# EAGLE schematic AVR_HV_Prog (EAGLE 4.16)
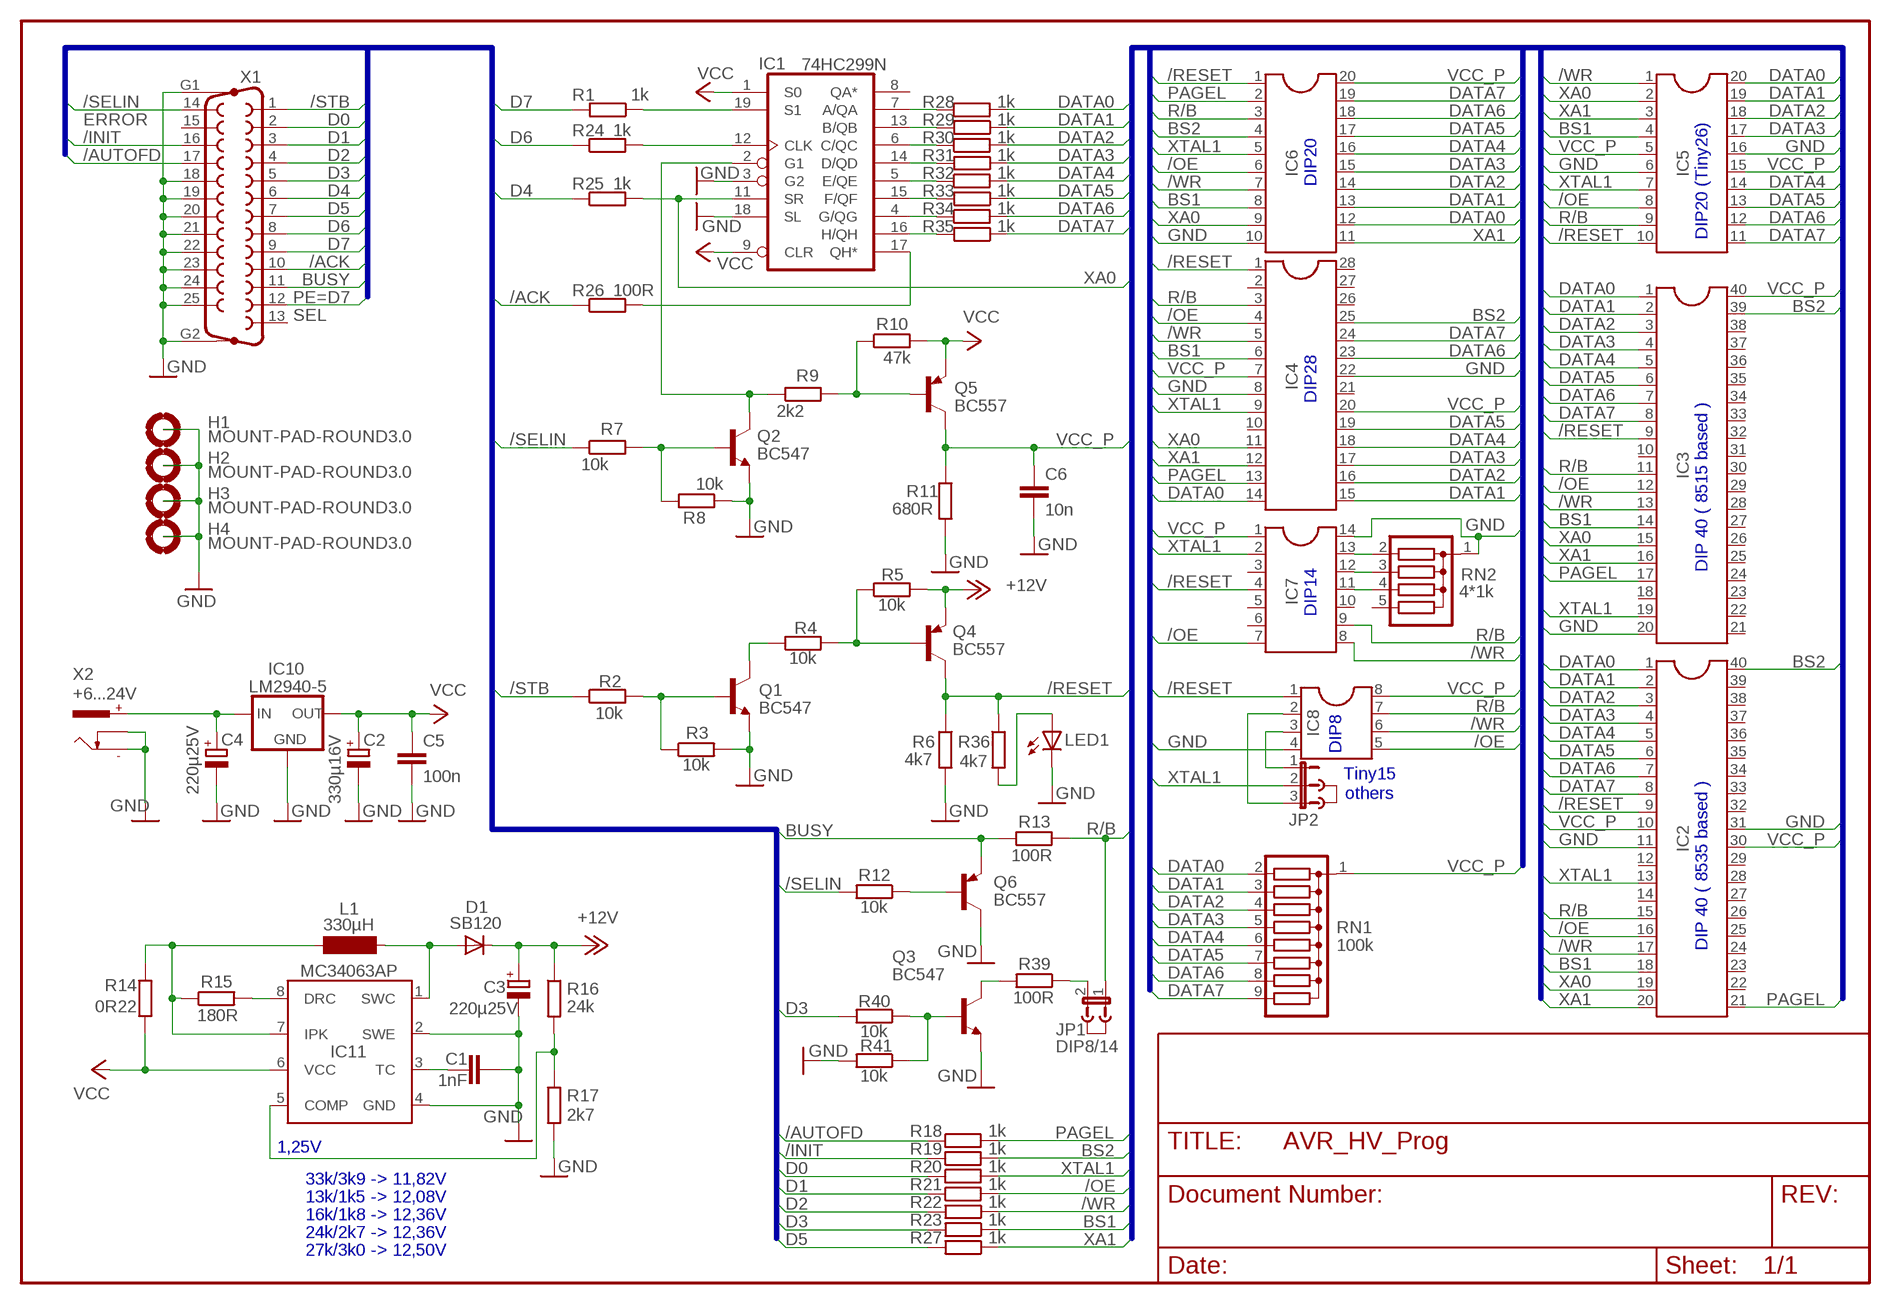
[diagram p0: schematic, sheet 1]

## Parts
C1  1nF  C-EU025-025X050  [C025-025X050]
C2  330µ16V  CPOL-EUE3.5-8  [E3,5-8]
C3  220µ25V  CPOL-EUE3.5-8  [E3,5-8]
C4  220µ25V  CPOL-EUE3.5-8  [E3,5-8]
C5  100n  C-EU050-024X044  [C050-024X044]
C6  10n  C-EU050-024X044  [C050-024X044]
D1  SB120  DIODE-D-2.5  [D-2.5]
H1  MOUNT-PAD-ROUND3.0  [3,0-PAD]
H2  MOUNT-PAD-ROUND3.0  [3,0-PAD]
H3  MOUNT-PAD-ROUND3.0  [3,0-PAD]
H4  MOUNT-PAD-ROUND3.0  [3,0-PAD]
IC1  74HC299N  [DIL20]
IC2  DIL40  [DIL40]
IC3  DIL40  [DIL40]
IC4  DIL28-3  [DIL28-3]
IC5  DIL20  [DIL20]
IC6  DIL20  [DIL20]
IC7  DIL14  [DIL14]
IC8  DIL8  [DIL08]
IC10  LM2940-5  78XXS  [78XXS]
IC11  MC34063AP  [DIL-08]
J1  JUMPER  [JUMP]
J2  JUMPER  [JUMP]
JP1  DIP8/14  JP1E  [JP1]
JP2  JP2E  [JP2]
L1  330µH  BS11  [BS11]
LED1  LED3MM  [LED3MM]
Q1  BC547  [TO92]
Q2  BC547  [TO92]
Q3  BC547  [TO92]
Q4  BC557  [TO92]
Q5  BC557  [TO92]
Q6  BC557  [TO92]
R1  1k  R-EU_0204/7  [0204/7]
R2  10k  R-EU_0207/2V  [0207/2V]
R3  10k  R-EU_0207/2V  [0207/2V]
R4  10k  R-EU_0207/2V  [0207/2V]
R5  10k  R-EU_0207/2V  [0207/2V]
R6  4k7  R-EU_0207V  [0207V]
R7  10k  R-EU_0207/10  [0207/10]
R8  10k  R-EU_0207/2V  [0207/2V]
R9  2k2  R-EU_0207/2V  [0207/2V]
R10  47k  R-EU_0207/2V  [0207/2V]
R11  680R  R-EU_0207/2V  [0207/2V]
R12  10k  R-EU_0207/10  [0207/10]
R13  100R  R-EU_0207/10  [0207/10]
R14  0R22  R-EU_0207V  [0207V]
R15  180R  R-EU_0207V  [0207V]
R16  24k  R-EU_0207V  [0207V]
R17  2k7  R-EU_0207V  [0207V]
R18  1k  R-EU_0207/10  [0207/10]
R19  1k  R-EU_0207/10  [0207/10]
R20  1k  R-EU_0207/10  [0207/10]
R21  1k  R-EU_0207/2V  [0207/2V]
R22  1k  R-EU_0207/2V  [0207/2V]
R23  1k  R-EU_0207V  [0207V]
R24  1k  R-EU_0207/10  [0207/10]
R25  1k  R-EU_0207/10  [0207/10]
R26  100R  R-EU_0204/7  [0204/7]
R27  1k  R-EU_0207/10  [0207/10]
R28  1k  R-EU_0207/2V  [0207/2V]
R29  1k  R-EU_0207/2V  [0207/2V]
R30  1k  R-EU_0207/2V  [0207/2V]
R31  1k  R-EU_0207/2V  [0207/2V]
R32  1k  R-EU_0207/2V  [0207/2V]
R33  1k  R-EU_0207/2V  [0207/2V]
R34  1k  R-EU_0207/2V  [0207/2V]
R35  1k  R-EU_0207/2V  [0207/2V]
R36  4k7  R-EU_0207V  [0207V]
R39  100R  R-EU_0207/10  [0207/10]
R40  10k  R-EU_0207/2V  [0207/2V]
R41  10k  R-EU_0207/2V  [0207/2V]
RN1  100k  G08R  [SIL9]
RN2  4*1k  G04R  [SIL5]
X1  F25HP  [F25HP]
X2  +6...24V  NEB21R  [NEB21R]

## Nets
+12V: C3.+ D1.C Q4.1(E) R5.2 R16.1
/ACK: R26.1 X1.10
/AUTOFD: R18.1 X1.17
/INIT: R19.1 X1.16
/OE: IC2.16 IC3.12 IC4.4 IC5.8 IC6.6 IC7.7 IC8.5 R21.2
/RESET: IC2.9 IC3.9 IC4.1 IC5.10 IC6.1 IC7.4 IC8.1 Q4.3(C) R6.1 R36.1
/SELIN: R7.1 R12.2 X1.14
/STB: R2.1 X1.1
/WR: IC2.17 IC3.13 IC4.5 IC5.1 IC6.7 IC7.8 IC8.6 R22.1
BS1: IC2.18 IC3.14 IC4.6 IC5.4 IC6.8 R23.1
BS2: IC2.40 IC3.39 IC4.25 IC6.4 R19.2
BUSY: Q6.1(E) R13.1 X1.11
D0: R20.1 X1.2
D1: R21.1 X1.3
D2: R22.2 X1.4
D3: R23.2 R40.2 X1.5
D4: R25.1 X1.6
D5: R27.2 X1.7
D6: R24.1 X1.8
D7: R1.2 X1.9 X1.12
DATA0: IC2.1 IC3.1 IC4.14 IC5.20 IC6.12 R28.2 RN1.2
DATA1: IC2.2 IC3.2 IC4.15 IC5.19 IC6.13 R29.1 RN1.3
DATA2: IC2.3 IC3.3 IC4.16 IC5.18 IC6.14 R30.2 RN1.4
DATA3: IC2.4 IC3.4 IC4.17 IC5.17 IC6.15 R31.1 RN1.5
DATA4: IC2.5 IC3.5 IC4.18 IC5.14 IC6.16 R32.2 RN1.6
DATA5: IC2.6 IC3.6 IC4.19 IC5.13 IC6.17 R33.1 RN1.7
DATA6: IC2.7 IC3.7 IC4.23 IC5.12 IC6.18 R34.2 RN1.8
DATA7: IC2.8 IC3.8 IC4.24 IC5.11 IC6.19 R35.1 RN1.9
GND: C1.2 C2.- C3.- C4.- C5.2 C6.2 H1.B3,0(MOUNT) H2.B3,0(MOUNT) H3.B3,0(MOUNT) H4.B3,0(MOUNT) IC1.3(G2) IC1.18(SL) IC2.11 IC2.31 IC3.20 IC4.8 IC4.22 IC5.6 IC5.16 IC6.10 IC7.14 IC8.4 IC10.GND IC11.2(SWE) IC11.4(GND) LED1.K(C) Q1.1(E) Q2.1(E) Q3.1(E) Q6.3(C) R3.2 R6.2 R8.1 R11.2 R17.2 R41.2 RN2.1 X1.18 X1.19 X1.20 X1.21 X1.22 X1.23 X1.24 X1.25 X1.G1 X1.G2 X2.- X2.C
N$1: IC1.17(QH*) R26.2
N$2: IC7.13 RN2.2
N$3: IC1.12(CLK) R24.2
N$4: IC1.19(S1) R1.1
N$5: IC1.7(A/QA) R28.1
N$6: IC1.13(B/QB) R29.2
N$7: IC1.6(C/QC) R30.1
N$8: IC1.14(D/QD) R31.2
N$9: IC11.8(DRC) R15.2
N$10: IC1.5(E/QE) R32.1
N$11: C1.1 IC11.3(TC)
N$12: IC11.7(IPK) L1.1 R14.2 R15.1
N$13: D1.A IC11.1(SWC) L1.2
N$14: Q1.3(C) R4.1
N$15: Q4.2(B) R4.2 R5.1
N$16: Q1.2(B) R2.2 R3.1
N$17: IC11.5(COMP) R16.2 R17.1
N$18: IC8.2 JP2.3
N$19: Q5.2(B) R9.2 R10.1
N$20: Q6.2(B) R12.1
N$21: IC1.15(F/QF) R33.2
N$22: IC1.2(G1) Q2.3(C) R9.1
N$23: Q2.2(B) R7.2 R8.2
N$24: IC1.4(G/QG) R34.1
N$25: IC1.16(H/QH) R35.2
N$26: IC7.12 RN2.3
N$27: IC7.11 RN2.4
N$28: JP1.2 R39.1
N$29: Q3.3(C) R39.2
N$30: Q3.2(B) R40.1 R41.1
N$31: IC8.3 JP2.1
N$32: LED1.A R36.2
PAGEL: IC2.21 IC3.17 IC4.13 IC6.2 R18.2
R/B: IC2.15 IC3.11 IC4.3 IC5.9 IC6.3 IC7.9 IC8.7 JP1.1 R13.2
U_IN: C4.+ IC10.IN X2.+
VCC: C2.+ C5.1 IC1.1(S0) IC1.9(CLR) IC10.OUT IC11.6(VCC) Q5.1(E) R10.2 R14.1
VCC_P: C6.1 IC2.10 IC2.30 IC3.40 IC4.7 IC4.20 IC5.5 IC5.15 IC6.20 IC7.1 IC8.8 Q5.3(C) R11.1 RN1.1
XA0: IC1.11(SR) IC2.19 IC3.15 IC4.11 IC5.2 IC6.9 R25.2
XA1: IC2.20 IC3.16 IC4.12 IC5.3 IC6.11 R27.1
XTAL1: IC2.13 IC3.19 IC4.9 IC5.7 IC6.5 IC7.2 JP2.2 R20.2
Unconnected: IC1.8(QA*) IC2.12 IC2.14 IC2.22 IC2.23 IC2.24 IC2.25 IC2.26 IC2.27 IC2.28 IC2.29 IC2.32 IC2.33 IC2.34 IC2.35 IC2.36 IC2.37 IC2.38 IC2.39 IC3.10 IC3.18 IC3.21 IC3.22 IC3.23 IC3.24 IC3.25 IC3.26 IC3.27 IC3.28 IC3.29 IC3.30 IC3.31 IC3.32 IC3.33 IC3.34 IC3.35 IC3.36 IC3.37 IC3.38 IC4.2 IC4.10 IC4.21 IC4.26 IC4.27 IC4.28 IC7.3 IC7.5 IC7.6 IC7.10 RN2.5 X1.13 X1.15

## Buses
PROGBUS:DATA0,DATA1,DATA2,DATA3,DATA4,DATA5,DATA6,DATA7,/RESET,R/B,/OE,/WR,BS1,BS2,XA0,XA1,PAGEL,XTAL1,GND,VCC_P
LPTBUS:D0,D1,D2,D3,D4,D5,D6,D7,/STB,/ACK,BUSY,PE,/SELIN,/INIT,/AUTOFD

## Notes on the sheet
- ERROR
- DIP20
- DIP20 (Tiny26)
- PE=
- SEL
- DIP28
- DIP 40 ( 8515 based )
- DIP14
- DIP8
- Tiny15
- others
- DIP 40 ( 8535 based )
- 1,25V
- 33k/3k9 -> 11,82V
- 13k/1k5 -> 12,08V
- 16k/1k8 -> 12,36V
- 24k/2k7 -> 12,36V
- 27k/3k0 -> 12,50V

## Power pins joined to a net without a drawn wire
GND: IC1.10(GND)
VCC: IC1.20(VCC)

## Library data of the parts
C1 C5 C6 = rcl:C-EU: CAPACITOR, European symbol
C2-C4 = rcl:CPOL-EU: POLARIZED CAPACITOR, European symbol
D1 = diode:DIODE-: DIODE
H1-H4 = holes:MOUNT-PAD-ROUND: MOUNTING PAD, round
IC1 = 74xx-eu:74*299: 8-bit universal SHIFT/STORAGE REGISTER
IC2 IC3 = ic-package:DIL40: Dual In Line
IC4 = ic-package:DIL28: Dual In Line
IC5 IC6 = ic-package:DIL20: Dual In Line
IC7 = ic-package:DIL14: Dual In Line
IC8 = ic-package:DIL8: Dual In Line
IC10 = v-reg:78XXS: VOLTAGE REGULATOR
IC11 = v-reg-3:MC34063A: 1.5A Step-Up/Down/Inverting Switching Regulator NPN Darlington Switch, Vin 3V to 40V, Current Limiter Input, adjustable Frequency up to 100kHz
J1 J2 = jumper:JUMPER: JUMPER header
JP1 = jumper:JP1E: JUMPER
JP2 = jumper:JP2E: JUMPER
L1 = inductor-neosid:BS: INDUCTOR
LED1 = led:LED: LED
Q1-Q3 = transistor-npn:BC547*: NPN Transistor
Q4-Q6 = transistor-pnp:BC557: PNP Transistor
R1-R36 R39-R41 = rcl:R-EU_: RESISTOR, European symbol
RN1 = resistor-sil:G08R: SIL RESISTOR
RN2 = resistor-sil:G04R: SIL RESISTOR
X1 = con-subd:F25HP: SUB-D
X2 = con-lumberg:NEB21R: Klinkeneinbaukupplung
